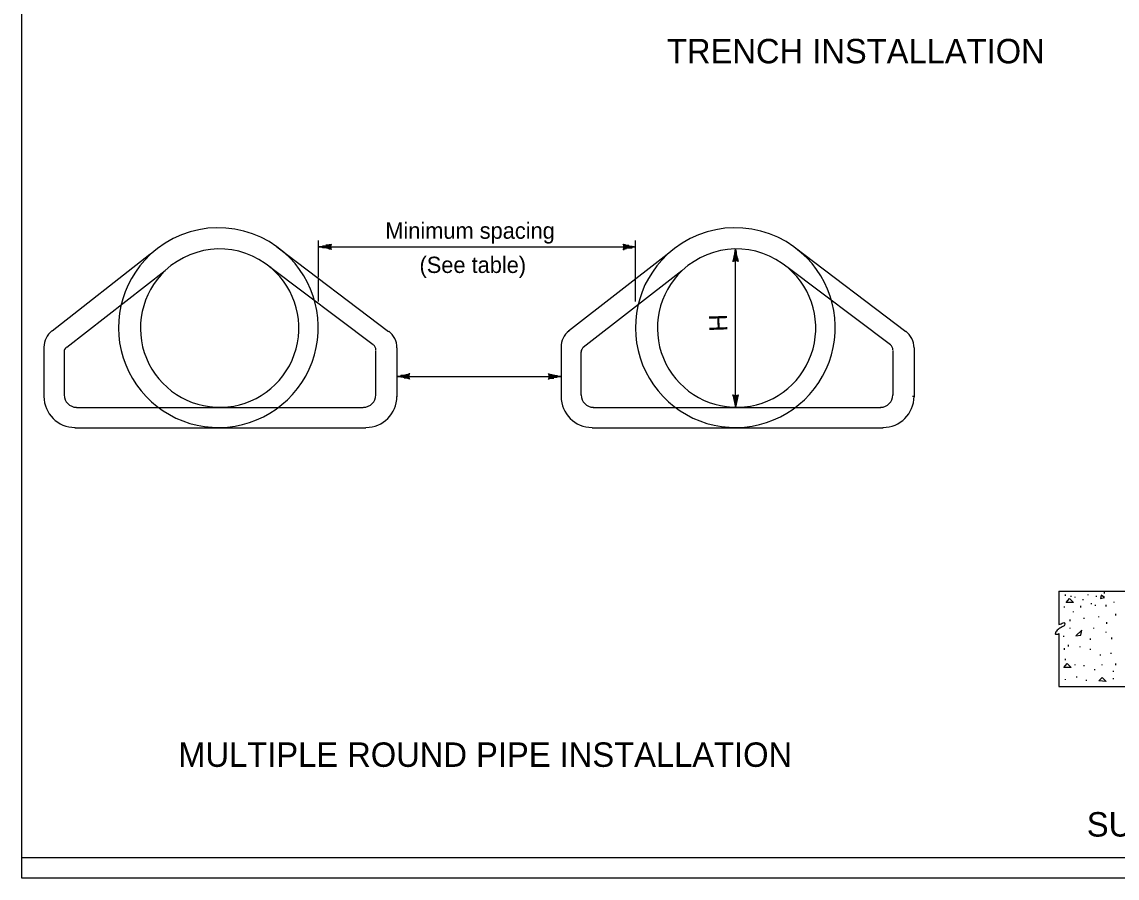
# Model space of a CAD drawing. Extents: x 0 to 390, y 0 to 265.
# Drawn here: x 0 to 134.4, y 0 to 105.1 of the extents above; entities that cross this region are included whole.
import ezdxf

# ---------------------------------------------------------------- set-up
doc = ezdxf.new("R2010")
doc.units = 0
doc.layers.add('D_Details', color=7, linetype='Continuous')
doc.layers.add('Default', color=7, linetype='Continuous')

msp = doc.modelspace()

# ---------------------------------------------------------------- linework, layer by layer
at = {"layer": 'D_Details'}
for p, q in [((36.4, 73.8), (36.4, 78.3)), ((75.3, 70.8), (75.3, 78.3)), ((31.3, 77.5), (45, 67.1)), ((36.4, 77.5), (75.3, 77.5)), ((87.6, 57.8), (87.6, 77.2)), ((94.8, 77.5), (108.5, 67.1)), ((3.7, 67.2), (15.7, 76.6)), ((67.1, 67.2), (79.2, 76.6)), ((5.5, 65.2), (17.6, 74.6)), ((30.4, 75.1), (43.1, 65.5)), ((68.9, 65.2), (81, 74.6)), ((93.9, 75.1), (106.6, 65.5)), ((36.4, 70.8), (36.4, 73.5)), ((2.7, 65.2), (2.7, 59.1)), ((5.2, 64.6), (5.2, 59.3)), ((43.4, 64.8), (43.4, 59.3)), ((46, 65.1), (46, 59.1)), ((66.2, 65.2), (66.2, 59.1)), ((68.6, 64.6), (68.6, 59.3)), ((106.9, 64.8), (106.9, 59.3)), ((109.5, 65.1), (109.5, 59.1)), ((46, 61.6), (66.2, 61.6)), ((109.4, 59.1), (109.4, 59.2)), ((6.7, 57.8), (41.9, 57.8)), ((70.1, 57.8), (105.4, 57.8)), ((6.5, 55.3), (42.2, 55.3)), ((70, 55.3), (105.7, 55.3)), ((127.27, 35.24), (127.27, 31.14)), ((127.27, 35.24), (139.87, 35.24)), ((132.87, 34.94), (132.87, 35.14)), ((128.07, 34.64), (128.07, 34.84)), ((128.77, 34.54), (128.77, 34.64)), ((129.27, 34.44), (129.27, 34.54)), ((130.27, 34.14), (130.27, 34.24)), ((130.87, 34.74), (130.87, 34.84)), ((131.27, 33.64), (131.27, 33.74)), ((131.87, 34.54), (131.87, 34.64)), ((134.07, 33.84), (134.07, 33.94)), ((127.97, 33.24), (127.97, 33.34)), ((129.07, 32.64), (129.07, 32.74)), ((129.97, 33.24), (129.97, 33.44)), ((131.77, 33.44), (131.77, 33.54)), ((133.07, 33.34), (133.07, 33.54)), ((134.27, 32.24), (134.27, 32.44)), ((128.67, 31.54), (128.67, 31.74)), ((130.37, 31.84), (130.37, 31.94)), ((132.17, 32.04), (132.17, 32.14)), ((133.17, 31.24), (133.17, 31.44)), ((127.27, 30.04), (127.27, 23.54)), ((127.87, 29.64), (127.87, 29.74)), ((128.67, 30.64), (128.67, 30.74)), ((131.57, 30.64), (131.57, 30.74)), ((133.07, 30.14), (133.07, 30.24)), ((127.97, 28.04), (127.97, 28.24)), ((128.47, 28.44), (128.47, 28.64)), ((129.87, 28.34), (129.87, 28.44)), ((131.17, 29.24), (131.17, 29.44)), ((133.77, 29.34), (133.77, 29.54)), ((128.07, 26.74), (128.07, 26.94)), ((131.17, 28.04), (131.17, 28.14)), ((132.37, 27.34), (132.37, 27.44)), ((133.67, 27.54), (133.67, 27.64)), ((129.27, 26.14), (129.27, 26.24)), ((130.37, 26.04), (130.37, 26.14)), ((131.67, 25.54), (131.67, 25.64)), ((132.57, 26.14), (132.57, 26.24)), ((134.27, 26.14), (134.27, 26.34)), ((128.07, 24.34), (128.07, 24.44)), ((129.47, 24.64), (129.47, 24.74)), ((130.67, 24.24), (130.67, 24.34)), ((133.97, 25.34), (133.97, 25.44)), ((133.97, 24.44), (133.97, 24.54)), ((127.27, 23.54), (165.07, 23.54))]:
    msp.add_line(p, q, dxfattribs=at)
for points in [[(37.9, 77.5), (37.9, 77.5), (36.4, 77.5), (36.4, 77.5)], [(37.9, 77.6), (36.9, 77.6)], [(37.9, 77.4), (36.9, 77.4)], [(37.9, 77.7), (37.3, 77.7)], [(37.9, 77.4), (37.3, 77.4)], [(37.9, 77.7), (37.6, 77.7)], [(37.9, 77.3), (37.6, 77.3)], [(37.9, 77.8), (37.9, 77.8)], [(37.9, 77.2), (37.9, 77.2)], [(73.8, 77.8), (73.9, 77.8)], [(73.8, 77.2), (73.9, 77.2)], [(73.9, 77.7), (74.2, 77.7)], [(73.9, 77.7), (74.5, 77.7)], [(73.9, 77.6), (74.9, 77.6)], [(73.9, 77.5), (73.9, 77.5), (75.3, 77.5), (75.3, 77.5)], [(73.9, 77.4), (74.9, 77.4)], [(73.9, 77.4), (74.5, 77.4)], [(73.9, 77.3), (74.2, 77.3)], [(87.5, 75.8), (87.5, 76.8)], [(87.6, 75.8), (87.6, 75.8), (87.6, 77.2), (87.6, 77.2)], [(87.7, 75.8), (87.7, 76.8)], [(87.3, 75.7), (87.3, 75.8)], [(87.4, 75.8), (87.4, 76.4)], [(87.4, 75.8), (87.4, 76.1)], [(87.7, 75.8), (87.7, 76.4)], [(87.8, 75.8), (87.8, 76.1)], [(87.9, 75.7), (87.9, 75.8)], [(47.6, 61.9), (47.5, 61.9)], [(64.6, 61.9), (64.7, 61.9)], [(47.5, 61.6), (47.5, 61.6), (46, 61.6), (46, 61.6)], [(47.5, 61.7), (46.5, 61.7)], [(47.5, 61.5), (46.5, 61.5)], [(47.5, 61.7), (46.9, 61.7)], [(47.5, 61.4), (46.9, 61.4)], [(47.5, 61.8), (47.2, 61.8)], [(47.5, 61.4), (47.2, 61.4)], [(47.6, 61.3), (47.5, 61.3)], [(64.6, 61.3), (64.7, 61.3)], [(64.7, 61.8), (65, 61.8)], [(64.7, 61.7), (65.3, 61.7)], [(64.7, 61.7), (65.7, 61.7)], [(64.7, 61.6), (64.7, 61.6), (66.2, 61.6), (66.2, 61.6)], [(64.7, 61.5), (65.7, 61.5)], [(64.7, 61.4), (65.3, 61.4)], [(64.7, 61.4), (65, 61.4)], [(87.3, 59.3), (87.3, 59.3)], [(87.4, 59.3), (87.4, 58.7)], [(87.4, 59.3), (87.4, 59)], [(87.5, 59.3), (87.5, 58.3)], [(87.6, 59.3), (87.6, 59.3), (87.6, 57.8), (87.6, 57.8)], [(87.7, 59.3), (87.7, 58.7)], [(87.7, 59.3), (87.7, 58.3)], [(87.8, 59.3), (87.8, 59)], [(87.9, 59.3), (87.9, 59.3)]]:
    msp.add_lwpolyline(points, dxfattribs=at)
for points in [[(128.17, 33.84), (128.57, 34.34), (129.07, 33.84)], [(132.37, 34.34), (132.87, 34.44), (132.47, 34.74)], [(129.97, 29.84), (130.07, 30.44), (129.37, 29.74)], [(127.87, 25.84), (128.27, 26.34), (128.77, 25.84)], [(132.17, 24.24), (132.57, 24.64), (133.07, 24.14)]]:
    msp.add_lwpolyline(points, close=True, dxfattribs=at)
for centre, radius, start, end in [((24.11, 67.59), 12.26, 48.6425, 133.035), ((87.56, 67.59), 12.26, 48.6425, 133.035), ((24.11, 67.59), 12.26, 133.035, 48.6425), ((24.27, 67.53), 9.72, 49.4539, 133.3428), ((34.84, 88.83), 11.43, 278, 285.8117), ((34.84, 66.19), 11.43, 74.1865, 82), ((38.59, 77.51), 0.71, 153.215, 206.785), ((73.17, 77.51), 0.71, 333.215, 26.785), ((76.92, 88.83), 11.43, 254.1865, 262), ((76.92, 66.19), 11.43, 98, 105.8117), ((87.56, 67.59), 12.26, 133.035, 48.6425), ((87.72, 67.53), 9.72, 49.4539, 133.3428), ((76.25, 78.75), 11.43, 344.5649, 352.3784), ((98.89, 78.9), 11.43, 188.3784, 196.1901), ((87.6, 75.08), 0.71, 63.5934, 117.1634), ((24.27, 67.53), 9.72, 133.3428, 49.4539), ((87.72, 67.53), 9.72, 133.3428, 49.4539), ((5.25, 65.18), 2.54, 127.9489, 180), ((43.49, 65.12), 2.54, 0, 52.9314), ((68.71, 65.18), 2.54, 127.9489, 180), ((106.95, 65.12), 2.54, 0, 52.9314), ((5.93, 64.59), 0.762, 127.9489, 180), ((42.68, 64.85), 0.762, 0, 52.9314), ((69.39, 64.59), 0.762, 127.9489, 180), ((106.14, 64.85), 0.762, 0, 52.9314), ((44.44, 72.92), 11.43, 278, 285.8117), ((48.19, 61.6), 0.71, 153.215, 206.785), ((64.01, 61.6), 0.71, 333.215, 26.785), ((67.76, 72.92), 11.43, 254.1865, 262), ((44.44, 50.28), 11.43, 74.1865, 82), ((67.76, 50.28), 11.43, 98, 105.8117), ((6.7, 59.33), 1.52, 180, 270), ((41.92, 59.33), 1.52, 270, 0), ((70.15, 59.33), 1.52, 180, 270), ((87.58, 59.97), 0.71, 243.4637, 297.0337), ((76.28, 56.17), 11.43, 8.2487, 16.0603), ((98.92, 56.27), 11.43, 164.4352, 172.2487), ((105.38, 59.33), 1.52, 270, 0), ((6.52, 59.14), 3.81, 180, 270), ((42.22, 59.14), 3.81, 270, 0), ((69.98, 59.14), 3.81, 180, 270), ((105.68, 59.14), 3.81, 270, 0)]:
    msp.add_arc(centre, radius, start, end, dxfattribs=at)
msp.add_spline([(127.27, 31.14), (127.57, 31.24), (127.97, 31.34), (127.97, 31.04), (127.67, 30.84), (127.17, 30.54), (126.97, 30.34), (126.87, 29.94), (127.07, 29.94), (127.17, 29.94), (127.27, 30.04)], degree=3, dxfattribs=at)
at = {"layer": 'Default'}
for points in [[(0, 265), (326.25, 265), (326.25, 255), (390, 255), (390, 37.5), (315, 37.5), (315, 0), (0, 0)], [(0, 262.5), (326.25, 262.5), (326.25, 252.5), (390, 252.5), (390, 40), (315, 40), (315, 2.5), (0, 2.5)]]:
    msp.add_lwpolyline(points, close=True, dxfattribs=at)

# ---------------------------------------------------------------- texts
at = {"layer": 'D_Details'}
for s, height, p in [('TRENCH INSTALLATION', 3, (79.17, 100.04)), ('Minimum spacing', 1.9998, (44.6, 78.5)), ('(See table)', 1.9998, (48.8, 74.3)), ('MULTIPLE ROUND PIPE INSTALLATION', 3, (19.19, 13.66)), ('SUPPLEMENTAL CONCRETE PIPE TIE', 3, (130.7, 5.1))]:
    msp.add_text(s, height=height, dxfattribs=at).set_placement(p)
msp.add_text('H', height=2.22, rotation=272.0016, dxfattribs=at).set_placement((84.3, 69.2))

doc.saveas('drawing.dxf')
